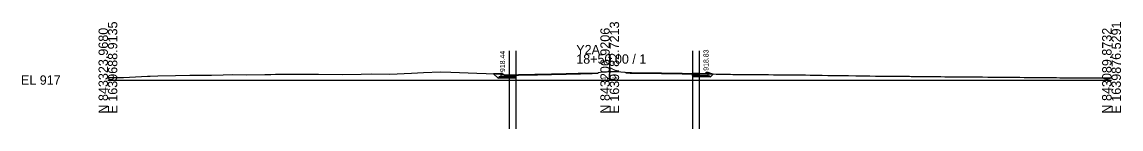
# Model space of a CAD drawing. Extents: x -26 to 303, y -10 to 10517.
# Drawn here: x -25.7 to 302.8, y 7985.4 to 8017.3 of the extents above; entities that cross this region are included whole.
import ezdxf

# ---------------------------------------------------------------- set-up
doc = ezdxf.new("R2010")
doc.units = 0
for name, color, linetype in [('Exist Cross Section Cell', 7, 'Continuous'), ('Exist XS Center Line Elevation Label', 7, 'Continuous'), ('Exist XS Ground Line', 7, 'Continuous'), ('Prop CMT Conc Surface', 7, 'Continuous'), ('Prop CMT Concrete Structures', 7, 'Continuous'), ('Prop CMT Pvmt Course 1', 7, 'Continuous'), ('Prop CMT Pvmt Course 1 CG', 7, 'Continuous'), ('Prop CMT Pvmt Course 2', 7, 'Continuous'), ('Prop CMT Pvmt Surface Overlay', 7, 'Continuous'), ('Prop CMT Slope Grass', 7, 'Continuous'), ('Prop CMT Subgrade Earthwork', 7, 'Continuous'), ('Prop XS Hydro Elevations', 7, 'Continuous'), ('Scratch_Level_0', 7, 'Continuous'), ('Scratch_Level_2', 7, 'Continuous')]:
    doc.layers.add(name, color=color, linetype=linetype)

msp = doc.modelspace()

# ---------------------------------------------------------------- linework, layer by layer
at = {"layer": 'Exist Cross Section Cell'}
for p, q in [((150, 8000), (150, 8007.68)), ((0, 8000), (150, 8000)), ((150, 8000), (300, 8000))]:
    msp.add_line(p, q, dxfattribs=at)
at = {"layer": 'Exist XS Ground Line'}
msp.add_lwpolyline([(0, 8000.77), (1.95, 8000.8), (4.65, 8000.79), (11.81, 8001.12), (12.28, 8001.12), (12.65, 8001.13), (14.95, 8001.25), (20.22, 8001.37), (24.44, 8001.42), (30.94, 8001.5), (34.45, 8001.56), (37.26, 8001.64), (41.56, 8001.6), (46.93, 8001.68), (48.67, 8001.68), (50.07, 8001.73), (55.79, 8001.76), (62.92, 8001.77), (70.02, 8001.62), (75.71, 8001.77), (78.91, 8001.82), (84.25, 8001.79), (90.73, 8002.08), (94.32, 8002.25), (99.45, 8002.5), (102.54, 8002.39), (110.28, 8002.08), (115.83, 8001.88), (118.05, 8001.78), (118.67, 8001.35), (119.77, 8001.39), (120.57, 8001.42), (121.5, 8001.45), (122.02, 8001.47), (122.75, 8001.49), (123.66, 8001.52), (124.53, 8001.54), (125.23, 8001.55), (127.66, 8001.58), (128.09, 8001.59), (128.43, 8001.6), (129.87, 8001.63), (131.65, 8001.67), (132.6, 8001.69), (134.84, 8001.75), (135.2, 8001.76), (135.65, 8001.77), (136.98, 8001.8), (138.04, 8001.83), (138.76, 8001.85), (139.65, 8001.87), (140.54, 8001.88), (141.25, 8001.89), (142.32, 8001.91), (143.65, 8001.94), (144.09, 8001.95), (144.72, 8001.97), (146.31, 8002.02), (146.65, 8002.23), (147.79, 8002.41), (148.38, 8002.5), (150, 8002.53), (150.34, 8002.53), (152.11, 8002.56), (154.48, 8002.37), (154.91, 8002.11), (156.09, 8002.09), (156.54, 8002.09), (157.27, 8002.08), (158.32, 8002.07), (159.64, 8002.05), (160.1, 8002.05), (160.47, 8002.05), (161.88, 8002.04), (163.67, 8002.03), (165.44, 8001.99), (166.88, 8001.97), (167.22, 8001.97), (167.64, 8001.96), (168.99, 8001.93), (170.08, 8001.92), (170.77, 8001.91), (171.63, 8001.89), (173.29, 8001.87), (175.63, 8001.85), (176.49, 8001.84), (179.74, 8001.81), (181.78, 8001.78), (182.93, 8001.77), (183.63, 8001.76), (185, 8001.73), (186.1, 8001.71), (186.78, 8001.7), (187.31, 8001.69), (188.57, 8001.68), (189.31, 8001.68), (191.62, 8001.66), (192.51, 8001.66), (195.24, 8001.64), (195.71, 8001.64), (197.45, 8001.62), (198.92, 8001.6), (199.62, 8001.6), (201.01, 8001.59), (202.12, 8001.6), (202.78, 8001.6), (203.61, 8001.59), (204.56, 8001.57), (205.32, 8001.56), (206.34, 8001.55), (207.61, 8001.53), (208.12, 8001.52), (208.53, 8001.51), (209.9, 8001.49), (211.73, 8001.46), (213.46, 8001.44), (215.23, 8001.4), (215.61, 8001.39), (217.01, 8001.38), (218.14, 8001.36), (218.79, 8001.35), (219.6, 8001.34), (220.57, 8001.33), (221.34, 8001.32), (223.6, 8001.29), (224.13, 8001.28), (224.55, 8001.27), (227.75, 8001.24), (229.46, 8001.21), (230.96, 8001.21), (231.6, 8001.2), (234.16, 8001.17), (235.59, 8001.16), (237.36, 8001.14), (238.35, 8001.13), (239.59, 8001.12), (240.13, 8001.11), (240.57, 8001.11), (243.77, 8001.08), (244.51, 8001.07), (246.97, 8001.04), (247.59, 8001.04), (249.02, 8001.04), (250.18, 8001.01), (250.8, 8001.01), (251.58, 8001), (252.58, 8001), (253.38, 8000.99), (254.36, 8000.98), (255.58, 8000.97), (256.59, 8000.96), (259.79, 8000.92), (261.47, 8000.92), (262.99, 8000.89), (263.58, 8000.89), (265.03, 8000.87), (266.2, 8000.87), (267.57, 8000.86), (269.4, 8000.85), (270.37, 8000.84), (271.57, 8000.83), (272.14, 8000.82), (272.6, 8000.82), (273.92, 8000.8), (275.79, 8000.78), (277.29, 8000.77), (279.01, 8000.76), (279.57, 8000.75), (282.22, 8000.73), (282.82, 8000.73), (283.56, 8000.72), (284.59, 8000.71), (285.42, 8000.71), (287.56, 8000.71), (288.62, 8000.7), (291.83, 8000.68), (292.91, 8000.68), (295.03, 8000.67), (295.56, 8000.66), (298.24, 8000.65), (299.55, 8000.65), (300, 8000.65)], dxfattribs=at)
at = {"layer": 'Prop CMT Conc Surface'}
for points in [[(117.95, 8001.44), (117.95, 8001.94), (117.45, 8001.94)], [(178.78, 8001.83), (178.78, 8002.33), (179.28, 8002.33)]]:
    msp.add_lwpolyline(points, dxfattribs=at)
at = {"layer": 'Prop CMT Concrete Structures'}
for points in [[(119.95, 8001.56), (117.95, 8001.44), (117.95, 8001.94), (117.45, 8001.94)], [(117.45, 8001.94), (117.45, 8000.93), (119.95, 8000.98)], [(176.78, 8001.95), (178.78, 8001.83), (178.78, 8002.33), (179.28, 8002.33)], [(179.28, 8002.33), (179.28, 8001.31), (176.78, 8001.36)]]:
    msp.add_lwpolyline(points, dxfattribs=at)
at = {"layer": 'Prop CMT Pvmt Course 1'}
for p, q in [((119.95, 8001.56), (121.95, 8001.6)), ((119.95, 8001.56), (119.95, 8001.31)), ((119.95, 8001.31), (121.95, 8001.35)), ((121.95, 8001.6), (121.95, 8001.35)), ((174.78, 8001.98), (174.78, 8001.73)), ((176.78, 8001.95), (174.78, 8001.98)), ((176.78, 8001.7), (174.78, 8001.73)), ((176.78, 8001.95), (176.78, 8001.7))]:
    msp.add_line(p, q, dxfattribs=at)
at = {"layer": 'Prop CMT Pvmt Course 1 CG'}
for p, q in [((119.95, 8000.98), (119.95, 8000.65)), ((119.95, 8000.65), (121.95, 8000.68)), ((121.95, 8001.02), (121.95, 8000.68)), ((174.78, 8001.4), (174.78, 8001.07)), ((176.78, 8001.03), (174.78, 8001.07)), ((176.78, 8001.37), (176.78, 8001.03))]:
    msp.add_line(p, q, dxfattribs=at)
for points in [[(119.95, 8000.98), (116.95, 8000.92), (116.61, 8000.58)], [(116.65, 8000.58), (119.95, 8000.65)], [(176.78, 8001.36), (179.78, 8001.3), (180.11, 8000.97)], [(180.07, 8000.97), (176.78, 8001.03)]]:
    msp.add_lwpolyline(points, dxfattribs=at)
at = {"layer": 'Prop CMT Pvmt Course 2'}
for p, q in [((119.95, 8000.98), (119.95, 8001.31)), ((119.95, 8000.98), (121.95, 8001.02)), ((121.95, 8001.02), (121.95, 8001.35)), ((174.78, 8001.4), (174.78, 8001.73)), ((176.78, 8001.37), (174.78, 8001.4)), ((176.78, 8001.37), (176.78, 8001.7))]:
    msp.add_line(p, q, dxfattribs=at)
at = {"layer": 'Prop CMT Pvmt Surface Overlay'}
for points in [[(121.95, 8001.6), (122.75, 8001.61), (123.66, 8001.64), (124.53, 8001.66), (125.23, 8001.68), (127.66, 8001.71), (128.09, 8001.71), (128.43, 8001.72), (129.86, 8001.75), (131.65, 8001.8), (132.6, 8001.82), (135.2, 8001.88), (135.65, 8001.89), (136.98, 8001.93), (138.04, 8001.96), (138.76, 8001.98), (139.65, 8001.99), (140.54, 8002.01), (141.25, 8002.02), (142.31, 8002.04), (143.65, 8002.07), (144.09, 8002.08), (144.72, 8002.1), (146.53, 8002.15)], [(154.7, 8002.23), (156.09, 8002.22), (156.55, 8002.21), (157.27, 8002.2), (158.32, 8002.19), (159.64, 8002.18), (160.1, 8002.18), (160.47, 8002.17), (161.88, 8002.17), (163.68, 8002.15), (165.44, 8002.11), (166.88, 8002.1), (167.22, 8002.09), (167.64, 8002.08), (169, 8002.06), (170.08, 8002.04), (170.77, 8002.03), (171.63, 8002.02), (173.29, 8002), (174.78, 8001.98)]]:
    msp.add_lwpolyline(points, dxfattribs=at)
at = {"layer": 'Prop CMT Slope Grass'}
for points in [[(117.45, 8001.94), (115.29, 8001.9)], [(179.28, 8002.33), (180.94, 8001.8)]]:
    msp.add_lwpolyline(points, dxfattribs=at)
at = {"layer": 'Prop CMT Subgrade Earthwork'}
for points in [[(119.95, 8000.65), (116.61, 8000.58), (115.29, 8001.9)], [(176.78, 8001.03), (180.11, 8000.97), (180.94, 8001.8)]]:
    msp.add_lwpolyline(points, dxfattribs=at)
at = {"layer": 'Scratch_Level_0'}
for p, q in [((119.95, 8008.74), (119.95, 7985.39)), ((121.95, 8008.74), (121.95, 7985.39)), ((174.78, 8008.74), (174.78, 7985.39)), ((176.78, 8008.74), (176.78, 7985.39))]:
    msp.add_line(p, q, dxfattribs=at)
at = {"layer": 'Scratch_Level_2'}
for p, q in [((121.95, 8001.47), (121.5, 8001.45)), ((180.94, 8001.8), (179.74, 8001.81))]:
    msp.add_line(p, q, dxfattribs=at)
for points in [[(115.29, 8001.9), (116.61, 8000.58), (119.95, 8000.65), (121.95, 8000.68), (121.95, 8001.47)], [(121.5, 8001.45), (120.57, 8001.42), (119.77, 8001.39), (118.67, 8001.35), (118.05, 8001.78), (115.83, 8001.88), (115.29, 8001.9)], [(115.29, 8001.9), (116.61, 8000.58), (119.95, 8000.65), (121.95, 8000.68), (121.95, 8001.47)], [(174.78, 8001.86), (174.78, 8001.07), (176.78, 8001.03), (180.11, 8000.97), (180.53, 8001.38), (180.94, 8001.8)], [(179.74, 8001.81), (176.49, 8001.84), (175.63, 8001.85), (174.78, 8001.86)], [(174.78, 8001.86), (174.78, 8001.07), (176.78, 8001.03), (180.11, 8000.97), (180.53, 8001.38), (180.94, 8001.8)]]:
    msp.add_lwpolyline(points, dxfattribs=at)

# ---------------------------------------------------------------- texts
at = {"layer": 'Exist Cross Section Cell'}
for s, p in [('E 1639688.9135', (2.8, 7990)), ('E 1639782.7213', (152.8, 7990)), ('E 1639876.5291', (302.8, 7990)), ('N 843323.9680', (0, 7990)), ('N 843206.9206', (150, 7990)), ('N 843089.8732', (300, 7990))]:
    msp.add_text(s, height=2.8, rotation=90, dxfattribs=at).set_placement(p)
for s, p in [('Y2A', (140, 8007.68)), ('18+50.00 / 1', (140, 8004.88)), ('EL 917', (-26, 7998.6))]:
    msp.add_text(s, height=2.8, dxfattribs=at).set_placement(p)
at = {"layer": 'Exist XS Center Line Elevation Label'}
msp.add_text('919.53', height=1, dxfattribs=at).set_placement((148.1, 7999.92))
at = {"layer": 'Prop XS Hydro Elevations'}
for s, p in [('918.44', (118.7, 8002.39)), ('918.83', (179.53, 8002.78))]:
    msp.add_text(s, height=1.5, rotation=90, dxfattribs=at).set_placement(p)

doc.saveas('drawing.dxf')
